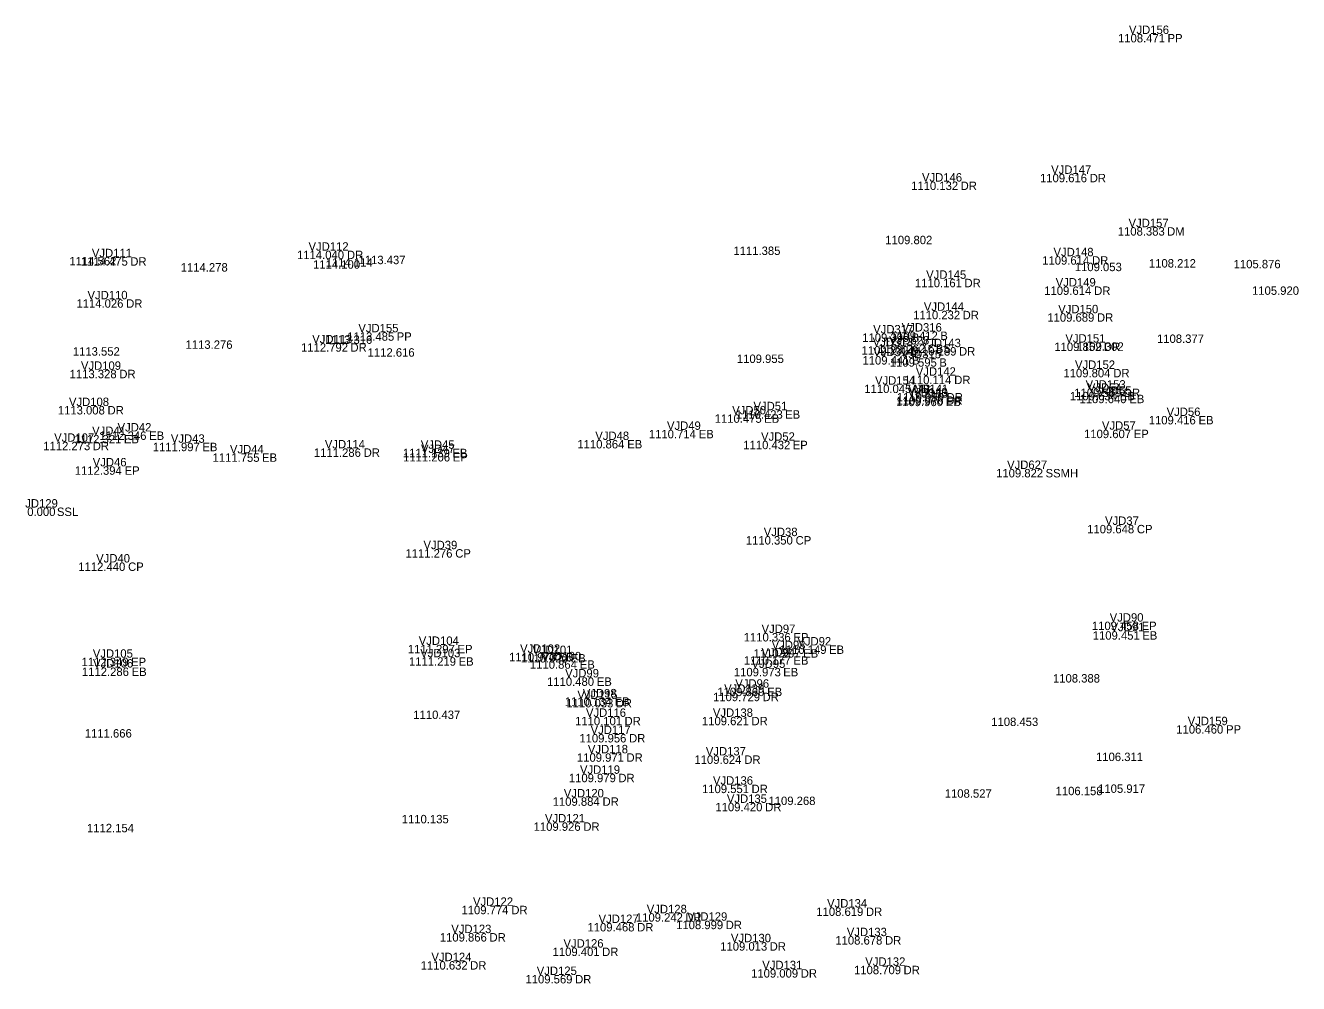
# Model space of a CAD drawing. Extents: x 1629927 to 1630657, y 484405 to 484576.
# Drawn here: x 1629927 to 1630078.2, y 484427.2 to 484541 of the extents above; entities that cross this region are included whole.
import ezdxf

# ---------------------------------------------------------------- set-up
doc = ezdxf.new("R2010")
doc.units = 0
for name, color, linetype in [('SV_X_Text_Comment', 7, 'Continuous'), ('SV_X_Text_Elevation', 7, 'Continuous'), ('SV_X_Text_Name', 7, 'Continuous')]:
    doc.layers.add(name, color=color, linetype=linetype)

msp = doc.modelspace()

# ---------------------------------------------------------------- texts
at = {"layer": 'SV_X_Text_Comment'}
for s, p in [('PP', (1630062.61, 484538.94)), ('DR', (1630053.37, 484522.34)), ('DR', (1630038.04, 484521.42)), ('DM', (1630062.56, 484516.01)), ('DR', (1629965.18, 484513.22)), ('DR', (1629939.46, 484512.44)), ('DR', (1630053.65, 484512.56)), ('DR', (1630038.5, 484509.88)), ('DR', (1630053.9, 484508.97)), ('DR', (1629938.97, 484507.45)), ('DR', (1630038.28, 484506.08)), ('DR', (1630054.23, 484505.79)), ('PP', (1629971.09, 484503.53)), ('B', (1630032.24, 484503.4)), ('B', (1630035.63, 484503.62)), ('DR', (1629965.6, 484502.23)), ('B', (1630032.16, 484501.88)), ('CBS', (1630034.14, 484502.09)), ('DR', (1630037.85, 484501.77)), ('DR', (1630055.05, 484502.31)), ('B', (1630032.27, 484500.7)), ('B', (1630035.51, 484500.45)), ('DR', (1629938.16, 484499.08)), ('DR', (1630037.28, 484498.38)), ('DR', (1630056.17, 484499.19)), ('MB', (1630032.48, 484497.32)), ('EB', (1630056.94, 484496.46)), ('DR', (1630057.42, 484496.85)), ('EB', (1630036.28, 484495.77)), ('DR', (1630036.34, 484495.94)), ('DR', (1630036.37, 484496.33)), ('EB', (1630058.07, 484496.12)), ('DR', (1629936.76, 484494.78)), ('EB', (1630014.72, 484493.79)), ('EB', (1630017.21, 484494.28)), ('EB', (1630066.29, 484493.6)), ('EB', (1630006.95, 484491.95)), ('EP', (1630058.6, 484491.97)), ('DR', (1629935, 484490.54)), ('EB', (1629938.7, 484491.35)), ('EB', (1629941.7, 484491.76)), ('EB', (1629948.02, 484490.42)), ('EB', (1629998.46, 484490.75)), ('EP', (1630018.11, 484490.66)), ('EB', (1629955.1, 484489.16)), ('DR', (1629967.17, 484489.75)), ('EB', (1629977.7, 484489.71)), ('EP', (1629977.75, 484489.2)), ('EP', (1629938.79, 484487.62)), ('SSMH', (1630048.13, 484487.31)), ('SSL', (1629930.75, 484482.73)), ('CP', (1630058.97, 484480.67)), ('CP', (1630018.45, 484479.34)), ('CP', (1629978.04, 484477.79)), ('CP', (1629939.2, 484476.21)), ('EP', (1630059.53, 484469.19)), ('EP', (1630018.19, 484467.84)), ('EB', (1630059.61, 484468.05)), ('EP', (1629978.31, 484466.43)), ('EB', (1630022.42, 484466.36)), ('EP', (1629939.56, 484464.91)), ('EB', (1629978.44, 484464.96)), ('EB', (1629990.29, 484465.49)), ('EB', (1629991.75, 484465.34)), ('EB', (1630018.19, 484465.08)), ('EB', (1630019.35, 484465.92)), ('EB', (1629939.62, 484463.74)), ('EB', (1629992.83, 484464.6)), ('EB', (1630016.98, 484463.7)), ('EB', (1629994.85, 484462.57)), ('EB', (1629996.97, 484460.2)), ('DR', (1630014.53, 484460.75)), ('EB', (1630015.08, 484461.35)), ('DR', (1629997.09, 484460.01)), ('DR', (1629998.14, 484457.89)), ('DR', (1630013.21, 484457.89)), ('DR', (1629998.68, 484455.85)), ('PP', (1630069.56, 484456.9)), ('DR', (1629998.37, 484453.56)), ('DR', (1630012.36, 484453.31)), ('DR', (1629997.41, 484451.13)), ('DR', (1630013.22, 484449.84)), ('DR', (1629995.53, 484448.33)), ('DR', (1630014.84, 484447.68)), ('DR', (1629993.25, 484445.36)), ('DR', (1629984.7, 484435.46)), ('DR', (1630005.36, 484434.58)), ('DR', (1630026.8, 484435.26)), ('DR', (1629999.64, 484433.42)), ('DR', (1630010.15, 484433.69)), ('DR', (1629982.11, 484432.22)), ('DR', (1630029.07, 484431.86)), ('DR', (1629995.48, 484430.5)), ('DR', (1630015.37, 484431.14)), ('DR', (1629979.81, 484428.89)), ('DR', (1629992.27, 484427.25)), ('DR', (1630019.06, 484427.94)), ('DR', (1630031.27, 484428.34))]:
    msp.add_text(s, height=1, dxfattribs=at).set_placement(p)
at = {"layer": 'SV_X_Text_Elevation'}
for s, p in [('1108.471', (1630056.73, 484538.94)), ('1109.616', (1630047.47, 484522.34)), ('1110.132', (1630032.17, 484521.42)), ('1108.383', (1630056.7, 484516.01)), ('1109.802', (1630029.1, 484514.99)), ('1114.040', (1629959.26, 484513.22)), ('1111.385', (1630011.07, 484513.71)), ('1114.562', (1629932.23, 484512.48)), ('1114.475', (1629933.59, 484512.44)), ('1114.278', (1629945.45, 484511.74)), ('1114.100', (1629961.16, 484512.08)), ('1114.114', (1629962.67, 484512.33)), ('1113.437', (1629966.56, 484512.62)), ('1109.614', (1630047.73, 484512.56)), ('1109.053', (1630051.6, 484511.79)), ('1108.212', (1630060.4, 484512.22)), ('1105.876', (1630070.46, 484512.13)), ('1110.161', (1630032.62, 484509.88)), ('1109.614', (1630047.97, 484508.97)), ('1105.920', (1630072.64, 484508.98)), ('1114.026', (1629933.07, 484507.45)), ('1110.232', (1630032.41, 484506.08)), ('1109.689', (1630048.34, 484505.79)), ('1113.276', (1629946.02, 484502.57)), ('1113.316', (1629962.61, 484503.16)), ('1113.485', (1629965.22, 484503.53)), ('1109.399', (1630026.36, 484503.4)), ('1109.412', (1630029.76, 484503.62)), ('1108.377', (1630061.36, 484503.27)), ('1113.552', (1629932.64, 484501.76)), ('1112.792', (1629959.73, 484502.23)), ('1112.616', (1629967.64, 484501.64)), ('1109.232', (1630026.28, 484501.88)), ('1109.262', (1630028.27, 484502.09)), ('1110.189', (1630031.97, 484501.77)), ('1109.852', (1630049.17, 484502.31)), ('1109.302', (1630051.83, 484502.34)), ('1109.955', (1630011.48, 484500.89)), ('1109.441', (1630026.39, 484500.7)), ('1109.595', (1630029.64, 484500.45)), ('1113.328', (1629932.26, 484499.08)), ('1110.114', (1630031.36, 484498.38)), ('1109.804', (1630050.25, 484499.19)), ('1110.045', (1630026.61, 484497.32)), ('1109.634', (1630051.02, 484496.46)), ('1109.569', (1630051.54, 484496.85)), ('1109.960', (1630030.37, 484495.77)), ('1109.976', (1630030.44, 484495.94)), ('1110.030', (1630030.46, 484496.33)), ('1109.640', (1630052.16, 484496.12)), ('1113.008', (1629930.86, 484494.78)), ('1110.475', (1630008.85, 484493.79)), ('1110.423', (1630011.35, 484494.28)), ('1109.416', (1630060.38, 484493.6)), ('1110.714', (1630001.03, 484491.95)), ('1109.607', (1630052.7, 484491.97)), ('1112.273', (1629929.13, 484490.54)), ('1112.321', (1629932.82, 484491.35)), ('1112.346', (1629935.8, 484491.76)), ('1111.997', (1629942.13, 484490.42)), ('1110.864', (1629992.54, 484490.75)), ('1110.432', (1630012.24, 484490.66)), ('1111.755', (1629949.23, 484489.16)), ('1111.286', (1629961.26, 484489.75)), ('1111.139', (1629971.82, 484489.71)), ('1111.206', (1629971.85, 484489.2)), ('1112.394', (1629932.87, 484487.62)), ('1109.822', (1630042.26, 484487.31)), ('0.000', (1629927.23, 484482.73)), ('1109.648', (1630053.07, 484480.67)), ('1110.350', (1630012.54, 484479.34)), ('1111.276', (1629972.13, 484477.79)), ('1112.440', (1629933.29, 484476.21)), ('1109.458', (1630053.63, 484469.19)), ('1110.336', (1630012.29, 484467.84)), ('1109.451', (1630053.73, 484468.05)), ('1111.297', (1629972.41, 484466.43)), ('1110.149', (1630016.54, 484466.36)), ('1112.349', (1629933.68, 484464.91)), ('1111.219', (1629972.55, 484464.96)), ('1110.973', (1629984.43, 484465.49)), ('1110.920', (1629985.84, 484465.34)), ('1110.177', (1630012.3, 484465.08)), ('1110.207', (1630013.46, 484465.92)), ('1112.286', (1629933.72, 484463.74)), ('1110.864', (1629986.91, 484464.6)), ('1109.973', (1630011.12, 484463.7)), ('1110.480', (1629988.94, 484462.57)), ('1108.388', (1630049.01, 484462.96)), ('1110.134', (1629991.05, 484460.2)), ('1109.729', (1630008.65, 484460.75)), ('1109.860', (1630009.16, 484461.35)), ('1110.437', (1629973.06, 484458.63)), ('1110.033', (1629991.23, 484460.01)), ('1110.101', (1629992.27, 484457.89)), ('1109.621', (1630007.33, 484457.89)), ('1108.453', (1630041.68, 484457.8)), ('1111.666', (1629934.06, 484456.43)), ('1109.956', (1629992.78, 484455.85)), ('1106.460', (1630063.65, 484456.9)), ('1109.971', (1629992.49, 484453.56)), ('1109.624', (1630006.44, 484453.31)), ('1106.311', (1630054.12, 484453.64)), ('1109.979', (1629991.53, 484451.13)), ('1109.551', (1630007.34, 484449.84)), ('1106.158', (1630049.32, 484449.59)), ('1105.917', (1630054.37, 484449.87)), ('1109.884', (1629989.61, 484448.33)), ('1109.268', (1630015.23, 484448.42)), ('1108.527', (1630036.16, 484449.29)), ('1109.420', (1630008.93, 484447.68)), ('1112.154', (1629934.32, 484445.19)), ('1110.135', (1629971.69, 484446.25)), ('1109.926', (1629987.35, 484445.36)), ('1109.774', (1629978.78, 484435.46)), ('1109.242', (1629999.49, 484434.58)), ('1108.619', (1630020.91, 484435.26)), ('1109.468', (1629993.74, 484433.42)), ('1108.999', (1630004.27, 484433.69)), ('1109.866', (1629976.21, 484432.22)), ('1108.678', (1630023.17, 484431.86)), ('1109.401', (1629989.6, 484430.5)), ('1109.013', (1630009.5, 484431.14)), ('1110.632', (1629973.94, 484428.89)), ('1109.569', (1629986.38, 484427.25)), ('1109.009', (1630013.17, 484427.94)), ('1108.709', (1630025.39, 484428.34))]:
    msp.add_text(s, height=1, dxfattribs=at).set_placement(p)
at = {"layer": 'SV_X_Text_Name'}
for s, p in [('VJD156', (1630058.03, 484539.94)), ('VJD146', (1630033.46, 484522.42)), ('VJD147', (1630048.79, 484523.34)), ('VJD157', (1630057.98, 484517.01)), ('VJD111', (1629934.9, 484513.44)), ('VJD112', (1629960.62, 484514.22)), ('VJD148', (1630049.07, 484513.56)), ('VJD145', (1630033.95, 484510.88)), ('VJD149', (1630049.33, 484509.97)), ('VJD110', (1629934.38, 484508.45)), ('VJD144', (1630033.68, 484507.08)), ('VJD150', (1630049.63, 484506.79)), ('VJD155', (1629966.54, 484504.53)), ('VJD317', (1630027.66, 484504.4)), ('VJD316', (1630031.05, 484504.62)), ('VJD113', (1629961.06, 484503.23)), ('VJD313', (1630027.61, 484502.88)), ('VJD628', (1630029.56, 484503.09)), ('VJD143', (1630033.31, 484502.77)), ('VJD151', (1630050.48, 484503.31)), ('VJD314', (1630027.67, 484501.7)), ('VJD315', (1630030.96, 484501.45)), ('VJD109', (1629933.6, 484500.08)), ('VJD152', (1630051.62, 484500.19)), ('VJD154', (1630027.88, 484498.32)), ('VJD142', (1630032.72, 484499.38)), ('VJD140', (1630031.75, 484496.94)), ('VJD141', (1630031.81, 484497.33)), ('VJD53', (1630032.53, 484496.77)), ('VJD153', (1630052.88, 484497.85)), ('VJD54', (1630053.14, 484497.46)), ('VJD55', (1630054.32, 484497.12)), ('VJD108', (1629932.18, 484495.78)), ('VJD51', (1630013.45, 484495.28)), ('VJD50', (1630010.92, 484494.79)), ('VJD56', (1630062.5, 484494.6)), ('VJD41', (1629934.93, 484492.35)), ('VJD42', (1629937.95, 484492.76)), ('VJD49', (1630003.18, 484492.95)), ('VJD57', (1630054.82, 484492.97)), ('VJD107', (1629930.42, 484491.54)), ('VJD43', (1629944.28, 484491.42)), ('VJD114', (1629962.56, 484490.75)), ('VJD45', (1629973.95, 484490.71)), ('VJD48', (1629994.67, 484491.75)), ('VJD52', (1630014.35, 484491.66)), ('VJD44', (1629951.29, 484490.16)), ('VJD47', (1629973.98, 484490.2)), ('VJD46', (1629935, 484488.62)), ('VJD627', (1630043.56, 484488.31)), ('JD129', (1629926.99, 484483.73)), ('VJD37', (1630055.19, 484481.67)), ('VJD38', (1630014.67, 484480.34)), ('VJD39', (1629974.27, 484478.79)), ('VJD40', (1629935.41, 484477.21)), ('VJD90', (1630055.74, 484470.19)), ('VJD97', (1630014.41, 484468.84)), ('VJD91', (1630055.85, 484469.05)), ('VJD104', (1629973.71, 484467.43)), ('VJD102', (1629985.74, 484466.49)), ('VJD101', (1629987.19, 484466.34)), ('VJD93', (1630015.61, 484466.92)), ('VJD92', (1630018.66, 484467.36)), ('VJD105', (1629935.01, 484465.91)), ('VJD106', (1629935.04, 484464.74)), ('VJD103', (1629973.89, 484465.96)), ('VJD100', (1629988.24, 484465.6)), ('VJD95', (1630013.22, 484464.7)), ('VJD94', (1630014.39, 484466.08)), ('VJD99', (1629991.09, 484463.57)), ('VJD139', (1630009.97, 484461.75)), ('VJD96', (1630011.29, 484462.35)), ('VJD115', (1629992.54, 484461.01)), ('VJD98', (1629993.19, 484461.2)), ('VJD116', (1629993.56, 484458.89)), ('VJD138', (1630008.63, 484458.89)), ('VJD159', (1630065, 484457.9)), ('VJD117', (1629994.11, 484456.85)), ('VJD118', (1629993.79, 484454.56)), ('VJD137', (1630007.79, 484454.31)), ('VJD119', (1629992.85, 484452.13)), ('VJD136', (1630008.64, 484450.84)), ('VJD120', (1629990.93, 484449.33)), ('VJD135', (1630010.29, 484448.68)), ('VJD121', (1629988.69, 484446.36)), ('VJD122', (1629980.15, 484436.46)), ('VJD134', (1630022.19, 484436.26)), ('VJD127', (1629995.06, 484434.42)), ('VJD128', (1630000.78, 484435.58)), ('VJD129', (1630005.58, 484434.69)), ('VJD123', (1629977.57, 484433.22)), ('VJD126', (1629990.89, 484431.5)), ('VJD130', (1630010.77, 484432.14)), ('VJD133', (1630024.53, 484432.86)), ('VJD124', (1629975.21, 484429.89)), ('VJD131', (1630014.49, 484428.94)), ('VJD132', (1630026.72, 484429.34)), ('VJD125', (1629987.72, 484428.25))]:
    msp.add_text(s, height=1, dxfattribs=at).set_placement(p)

doc.saveas('drawing.dxf')
